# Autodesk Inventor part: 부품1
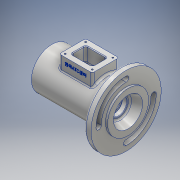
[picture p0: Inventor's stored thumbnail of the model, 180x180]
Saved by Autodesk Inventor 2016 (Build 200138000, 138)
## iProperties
Created: 2017-05
Part Number: 부품1
Material: 알루미늄 6061
Document SubType Name: Modeling
Designer: USER
Mass: 678.719 g
Surface Area: 617.984 cm^2
Volume: 251.378 cm^3
Density: 2.7 g/cm^3
Appearance: 알루미늄 - 평지
Author: USER
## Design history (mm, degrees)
sketch "스케치1"
  geometry: L1 (0, 0)-(0, 31); L2 (0, 31)-(102, 31); L3 (102, 31)-(102, 50); L4 (105, 53)-(112, 53); L5 (112, 53)-(112, 31); L6 (112, 31)-(115, 31); L7 (115, 31)-(115, 0); L8 (115, 0)-(0, 0); L9 (9, 0)-(9, 24); L10 (9, 24)-(12, 24); L11 (12, 24)-(12, 20); L12 (21, 20)-(21, 17.5); L13 (21, 17.5)-(24.25, 17.5); L14 (24.25, 17.5)-(24.25, 18.5); L15 (24.25, 18.5)-(26, 18.5); L16 (26, 18.5)-(26, 17.5); L17 (26, 17.5)-(36, 17.5); L18 (37, 18.5)-(37, 23); L19 (40, 26)-(72, 26); L20 (75, 23)-(75, 18.5); L21 (76, 17.5)-(86, 17.5); L22 (86, 17.5)-(86, 16.5); L23 (12, 20)-(21, 20); L24 (86, 16.5)-(88, 16.5); L25 (91, 13.5)-(91, 10); L26 (91, 10)-(93.7, 10); L27 (93.7, 10)-(93.7, 12.2); L28 (94, 12.5)-(100.3, 12.5); L29 (100.3, 12.5)-(101, 12.904); L30 (101, 12.904)-(101, 14.455); L31 (102.903, 17.248)-(115, 22); L32 (36, 17.5)-(37, 18.5); L33 (76, 17.5)-(75, 18.5); A1 r 3 centre (104, 14.455) between (102.903, 17.248) and (101, 14.455); A2 r 0.3 centre (94, 12.2) between (94, 12.5) and (93.7, 12.2); A3 r 3 centre (88, 13.5) between (91, 13.5) and (88, 16.5); A4 r 3 centre (40, 23) between (40, 26) and (37, 23); A5 r 3 centre (72, 23) between (75, 23) and (72, 26); A6 r 3 centre (105, 50) between (105, 53) and (102, 50); 4 further points
  constraints: 66 end point, 18 perpendicular, 12 point on circle, 12 point on line, 12 tangent, 6 centre point, 5 vertical, 3 equal radius, 3 horizontal
  dimensions: "d0" = 115 distance between parallel lines of L7 L1; "d1" = 3 distance between parallel lines of L7 L5; "d2" = 13 distance between parallel lines of L7 L3; "d3" = 106 diameter of L4 L8; "d4" = 62 diameter of L6 L8; "d5" = 62 diameter of L2 L8; "d7" = 48 diameter of L10 L8; "d10" = 3 distance between parallel lines of L11 L9; "d11" = 12 distance from line of L11.end L1; "d12" = 40 diameter of L23 L8; "d13" = 21 distance between parallel lines of L1 L12; "d14" = 35 diameter of L13 L8; "d15" = 37 diameter of L15 L8; "d16" = 1.75 distance between parallel lines of L16 L14; "d17" = 26 distance between parallel lines of L16 L1; "d18" = 35 diameter of L17 L8; "d19" = 52 diameter of L19 L8; "d20" = 11 distance between parallel lines of L18 L16; "d21" = 11 distance between parallel lines of L22 L20; "d22" = 35 diameter of L21 L8 (derived); "d24" = 38 distance between parallel lines of L20 L18; "d27" = 33 diameter of L24 L8; "d29" = 20 diameter of L26 L8; "d30" = 25 diameter of L28 L8; "d31" = 5 distance of L22.end point (91, 16.5); "d32" = 2.7 distance of L25.end L26.end; "d34" = 0.7 distance from line of L30 L28.end; "d35" = 30 deg angle of L29 L28; "d36" = 44 diameter of L31.end L8; "d37" = 33 diameter of point (101, 16.5) L8; "d38" = 14 distance between parallel lines of L7 L30; "d39" = 3 radius of A1; "d40" = 0.3 radius of A2; "d41" = 1 distance of L17.end point (37, 17.5); "d42" = 1 distance of L18.start point (37, 17.5) (= d41); "d43" = 1 distance of L21.start point (75, 17.5) (= d41); "d44" = 1 distance of L20.end point (75, 17.5) (= d43); "d45" = 3 radius of A6; "d98" = 7.3 distance between parallel lines of L30 L27 (derived)
revolve "회전1" sketch "스케치1" stored, may be unused: angle "d46" = 90 deg
hole "구멍1" diameter "d49" = 40.376; stored, may be unused: countersink angle "d53" = 90 deg, drill point angle "d55" = 0 deg; dims "d47" = 10, "d48" = 10, "d50" = 12, "d51" = 4, "d52" = 2, "d54" = 12
chamfer "모따기1" distance "d56" = 1; stored, may be unused: second distance "d57" = 2, angle "d58" = 45 deg
sketch "스케치2"
  geometry: L1 (0, 37.5)-(0, 45.5); L2 (37.5, 0)-(45.5, 0); L3 (-37.5, 0)-(-45.5, 0); L4 (0, -45.5)-(0, -37.5); C1 r 41.5 at (0, 0); C2 r 53 at (0, 0) reference; A1 r 4 centre (0, 41.5) between (0, 45.5) and (0, 37.5); A2 r 4 centre (41.5, 0) between (37.5, 0) and (45.5, 0); A3 r 4 centre (-41.5, 0) between (-37.5, 0) and (-45.5, 0); A4 r 4 centre (0, -41.5) between (0, -45.5) and (0, -37.5); A5 r 37.5 centre (0, 0) between (-37.5, 0) and (0, -37.5); A6 r 37.5 centre (0, 0) between (37.5, 0) and (0, 37.5); A7 r 45.5 centre (0, 0) between (-45.5, 0) and (0, -45.5); A8 r 45.5 centre (0, 0) between (45.5, 0) and (0, 45.5); 5 further points
  constraints: 16 point on circle, 9 centre point, 8 end point, 7 coincident, 4 midpoint, 2 horizontal alignment, 2 perpendicular, 2 vertical alignment, 1 horizontal, 1 vertical
  dimensions: "d59" = 83 diameter of C1; "d62" = 45.5 radius of A7; "d63" = 37.5 radius of A5; "d64" = 37.5 radius of A6; "d65" = 45.5 radius of A8
extrude "돌출1" cut sketch "스케치2" distance "d66" = 30; taper "d67" = 0 deg
node "작업 평면1"
sketch "스케치3"
  geometry: L1 (31, -20)-(81, -20); L2 (81, -20)-(81, 20); L3 (81, 20)-(31, 20); L4 (31, 20)-(31, -20); 4 further points
  constraints: 8 end point, 2 horizontal alignment, 2 midpoint, 2 parallel, 1 horizontal, 1 perpendicular, 1 vertical alignment
  dimensions: "d69" = 56 distance of point (56, 0) point (0, 0); "d70" = 40 distance of L3.end L1.start; "d71" = 50 distance of L1.start L1.end
extrude "돌출2" join sketch "스케치3" stored distance "d72" = 30; taper "d73" = 0 deg
sketch "스케치4"
  geometry: L1 (40, 11)-(72, 11); L2 (72, 11)-(72, -11); L3 (72, -11)-(40, -11); L4 (40, -11)-(40, 11); L5 (81, 20)-(31, 20) reference; L6 (31, 20)-(31, -20) reference; 5 further points
  constraints: 8 end point, 4 midpoint, 2 parallel, 1 horizontal, 1 horizontal alignment, 1 perpendicular, 1 vertical alignment
  dimensions: "d74" = 32 distance of L2.end L3.end; "d75" = 22 distance of L3.end L1.start
extrude "돌출3" cut sketch "스케치4" distance "d76" = 46; taper "d77" = 0 deg
sketch "스케치5"
  geometry: L1 (35.5, 15.5)-(76.5, 15.5); L2 (76.5, 15.5)-(76.5, -15.5); L3 (76.5, -15.5)-(35.5, -15.5); L4 (35.5, -15.5)-(35.5, 15.5); L5 (40, 11)-(72, 11) reference; L6 (40, -11)-(40, 11) reference; 9 further points
  constraints: 8 end point, 4 coincident, 4 midpoint, 2 parallel, 1 horizontal, 1 horizontal alignment, 1 perpendicular, 1 vertical alignment
  dimensions: "d78" = 41 distance of L2.end L3.end; "d79" = 31 distance of L3.end L1.start
hole "구멍2" sketch "스케치5" at (35.5, 15.5), (35.5, -15.5), (76.5, 15.5), (76.5, -15.5) diameter "d80" = 2.459; stored, may be unused: countersink angle "d84" = 90 deg, drill point angle "d86" = 120 deg; dims "d81" = 6, "d82" = 4, "d83" = 2, "d85" = 8
fillet "모깎기1" dims "d87" = 3
chamfer "모따기2" distance "d88" = 1; stored, may be unused: second distance "d89" = 2, angle "d90" = 45 deg
fillet "모깎기2" dims "d91" = 3
fillet "모깎기3" dims "d92" = 3
node "작업 평면2"
sketch "스케치6"
  geometry: L1 (0, -31)-(0, 31) reference; L2 (34, 44)-(78, 44) reference; 2 further points
  constraints: 1 other
  dimensions: "d94" = 56 distance from line of point (56, 36) L1; "d95" = 8 distance from line of point (56, 36) L2
feature "엠보싱1" sketch "스케치6" dims "d96" = 0.5, "d97" = 0
node "솔리드1"
other parameters: "d60" = 91, "d61" = 75, "d68" = 44
